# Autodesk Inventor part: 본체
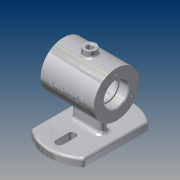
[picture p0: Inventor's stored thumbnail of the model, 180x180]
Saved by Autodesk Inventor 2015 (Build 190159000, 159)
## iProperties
Created: 2017-12
Part Number: 본체
Material: 알루미늄 6061
Document SubType Name: Modeling
Designer: 2-PC06
Mass: 465.966 g
Surface Area: 486.474 cm^2
Volume: 172.58 cm^3
Density: 2.7 g/cm^3
Appearance: 알루미늄 - 평지
Author: 2-PC06
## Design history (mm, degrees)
sketch "스케치1"
  geometry: L1 (-35, 42.426)-(-35, -42.426); L2 (35, 42.426)-(35, -42.426); L3 (0, 40)-(0, 24); L4 (5, 40)-(5, 24); L5 (-5, 24)-(-5, 40); L6 (0, -24)-(0, -40); L7 (5, -24)-(5, -40); L8 (-5, -40)-(-5, -24); A1 r 55 centre (0, 0) between (-35, -42.426) and (35, -42.426); A2 r 55 centre (0, 0) between (35, 42.426) and (-35, 42.426); A3 r 5 centre (0, 40) between (5, 40) and (-5, 40); A4 r 5 centre (0, 24) between (-5, 24) and (5, 24); A5 r 5 centre (0, -24) between (5, -24) and (-5, -24); A6 r 5 centre (0, -40) between (-5, -40) and (5, -40); 3 further points
  constraints: 20 end point, 12 point on circle, 8 tangent, 6 centre point, 3 vertical, 2 midpoint, 2 parallel, 2 point on line, 1 coincident, 1 concentric, 1 vertical alignment
  dimensions: "d1" = 70 distance between parallel lines of L2 L1; "d2" = 35 distance from line of point (0, 0) L1; "d4" = 110 diameter of A2; "d5" = 5 radius of A3; "d6" = 5 radius of A5; "d7" = 16 distance of L3.start L3.end; "d8" = 16 distance of L6.start L6.end; "d9" = 24 distance of point (0, 0) L3.end; "d10" = 24 distance of L6.start point (0, 0)
extrude "돌출1" new body sketch "스케치1" distance "d11" = 10; taper "d12" = 0 deg
sketch "스케치9"
  geometry: L1 (19, 10)-(19, 0) reference; L2 (19, 0)-(-19, 0) reference; L3 (-19, 0)-(-19, 10) reference; L4 (-19, 10)-(19, 10) reference; L5 (55, 10)-(55, 0) reference; L6 (55, 0)-(45, 0) reference; L7 (45, 0)-(45, 10) reference; L8 (45, 10)-(55, 10) reference; L9 (-55, 0)-(-55, 10) reference; L10 (-55, 10)-(-45, 10) reference; L11 (-45, 10)-(-45, 0) reference; L12 (-45, 0)-(-55, 0) reference; C1 r 30 at (0, 62); 2 further points
  constraints: 1 centre point, 1 midpoint, 1 vertical alignment
  dimensions: "d66" = 60 diameter of C1; "d67" = 62 distance from line of L12 C1.centre
extrude "돌출5" join sketch "스케치9" stored distance "d68" = 70; taper "d69" = 0 deg
sketch "스케치10"
  geometry: L1 (-15, 0)-(15, 0); L2 (-15, 5)-(15, 5); L3 (15, -5)-(-15, -5); A1 r 5 centre (-15, 0) between (-15, 5) and (-15, -5); A2 r 5 centre (15, 0) between (15, -5) and (15, 5); 1 further point
  constraints: 8 end point, 4 point on circle, 4 tangent, 2 centre point, 1 horizontal, 1 midpoint, 1 parallel
  dimensions: "d70" = 5 radius of A2; "d71" = 30 distance of L1.start L1.end
extrude "돌출6" join sketch "스케치10" stored distance "d72" = 70; taper "d73" = 0 deg
sketch "스케치11"
  geometry: L1 (35, 10)-(35, 0) reference; L2 (35, 0)-(-35, 0) reference; L3 (-35, 0)-(-35, 10) reference; L4 (-35, 10)-(-20, 10) reference; L5 (-20, 10)-(-20, 32) reference; L6 (-20, 32)-(-35, 32) reference; L7 (-35, 32)-(-35, 92) reference; L8 (-35, 92)-(35, 92) reference; L9 (35, 92)-(35, 32) reference; L10 (35, 32)-(20, 32) reference; L11 (20, 32)-(20, 10) reference; L12 (20, 10)-(35, 10) reference; L13 (35, 62)-(-35, 62); L14 (35, 62)-(35, 78); L15 (35, 32)-(35, 92) reference; L16 (35, 78)-(23.3, 78); L17 (23, 77.7)-(23, 76); L18 (23, 76)-(20, 76); L19 (20, 76)-(20, 84); L20 (17, 87)-(-17, 87); L21 (-20, 84)-(-20, 76); L22 (-20, 76)-(-23, 76); L23 (-23, 76)-(-23, 77.7); L24 (-23.3, 78)-(-35, 78); L25 (-35, 62)-(-35, 78); L26 (-35, 92)-(-35, 32) reference; A1 r 3 centre (17, 84) between (20, 84) and (17, 87); A2 r 3 centre (-17, 84) between (-17, 87) and (-20, 84); A3 r 0.3 centre (23.3, 77.7) between (23.3, 78) and (23, 77.7); A4 r 0.3 centre (-23.3, 77.7) between (-23, 77.7) and (-23.3, 78); 5 further points
  constraints: 24 end point, 14 point on line, 8 point on circle, 8 tangent, 6 perpendicular, 4 centre point, 2 equal radius, 2 midpoint, 1 collinear, 1 horizontal
  dimensions: "d74" = 32 diameter of L24 L13; "d75" = 28 diameter of L18 L13; "d76" = 50 diameter of L20 L13; "d77" = 12 distance of L14.end point (23, 78); "d78" = 12 distance of point (-23, 78) L24.end; "d79" = 3 distance of L17.end L18.end; "d80" = 3 distance of L21.end L22.end; "d81" = 40 distance of point (20, 87) point (-20, 87) (derived); "d82" = 3 radius of A1; "d83" = 0.3 radius of A3
revolve "회전2" sketch "스케치11" stored, may be unused: angle "d84" = 90 deg
node "작업 평면3"
sketch "스케치12"
  geometry: C1 r 8 at (0, 0); 1 further point
  constraints: 1 centre point, 1 coincident
  dimensions: "d86" = 16 diameter of C1
extrude "돌출7" join sketch "스케치12" stored distance "d87" = 70; taper "d88" = 0 deg
sketch "스케치13"
  geometry: 2 further points
  constraints: 1 coincident
hole "구멍3" sketch "스케치13" at (0, 0) diameter "d89" = 8; stored, may be unused: countersink angle "d93" = 90 deg, drill point angle "d95" = 118 deg; dims "d90" = 8, "d91" = 4, "d92" = 2, "d94" = 33
sketch "스케치14" dims "d96" = 46
  geometry: L1 (-62, -42.426)-(-62, 42.426) reference; L2 (-62, 42.426)-(-52, 42.426) reference; L3 (-52, 42.426)-(-52, -42.426) reference; L4 (-52, -42.426)-(-62, -42.426) reference; C1 r 16 at (0, 0) reference; C2 r 30 at (0, 0) reference; 3 further points
  constraints: 2 horizontal alignment, 1 coincident, 2 other
hole "구멍4" sketch "스케치14" at (23, 0) diameter "d97" = 3.242; stored, may be unused: countersink angle "d101" = 90 deg, drill point angle "d103" = 118 deg; dims "d98" = 8, "d99" = 4, "d100" = 2, "d102" = 10
chamfer "모따기2" distance "d107" = 1; stored, may be unused: second distance "d108" = 2, angle "d109" = 45 deg
fillet "모깎기4" dims "d110" = 5, "d111" = 3
fillet "모깎기5" dims "d112" = 3
node "작업 평면4"
sketch "스케치15"
  geometry: L1 (-35, 92)-(-35, 32) reference; 2 further points
  constraints: 1 other
  dimensions: "d114" = 35 distance from line of point (0, 62) L1; "d115" = 30 vertical distance of point (0, 62) L1.start
feature "엠보싱2" sketch "스케치15" dims "d1" = 70, "d2" = 35, "d4" = 110, "d116" = 0.5, "d117" = 0
node "솔리드1"
pattern_circular "원형 패턴2" dims angle "d105" = 360 deg
mirror "대칭2"
node "절단 모서리 투영4"
node "절단 모서리 투영5"
node "절단 모서리 투영6"
other parameters: "d85" = -99, "d113" = 85
